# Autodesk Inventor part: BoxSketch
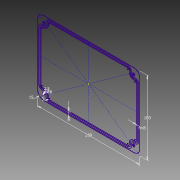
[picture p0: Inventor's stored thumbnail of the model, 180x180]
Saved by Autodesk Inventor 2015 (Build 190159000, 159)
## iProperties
Created: 2014-07
Part Number: BoxSketch
Material: Generic
Document SubType Name: Modeling
Designer: Gavin
Density: 1 g/cm^3
Appearance: Default
Author: Gavin
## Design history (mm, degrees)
sketch "Sketch1"
  geometry: L1 (135, 90)-(-135, 90); L2 (-150, 75)-(-150, -75); L3 (-135, -90)-(135, -90); L4 (150, -75)-(150, 75); L5 (150, 90)-(-150, -90); L6 (-150, 90)-(150, -90); L7 (121, -82)-(-121, -82); L8 (-142, -61)-(-142, 61); L9 (-121, 82)-(121, 82); L10 (142, 61)-(142, -61); L11 (124, -79)-(124, -75); L12 (135, -64)-(139, -64); L13 (0, -90)-(0, 90); L14 (150, 0)-(-150, 0); L15 (-124, -79)-(-124, -75); L16 (-135, -64)-(-139, -64); L17 (124, 79)-(124, 75); L18 (135, 64)-(139, 64); L19 (-124, 79)-(-124, 75); L20 (-135, 64)-(-139, 64); L21 (-121, -84.5)-(121, -84.5); L22 (126.5, -79)-(126.5, -75); L23 (135, -66.5)-(139, -66.5); L24 (144.5, -61)-(144.5, 61); L25 (139, 66.5)-(135, 66.5); L26 (126.5, 75)-(126.5, 79); L27 (121, 84.5)-(-121, 84.5); L28 (-126.5, 79)-(-126.5, 75); L29 (-135, 66.5)-(-139, 66.5); L30 (-144.5, 61)-(-144.5, -61); L31 (-139, -66.5)-(-135, -66.5); L32 (-126.5, -75)-(-126.5, -79); L33 (121, -87.5)-(-121, -87.5); L34 (-129.5, -79)-(-129.5, -75); L35 (-135, -69.5)-(-139, -69.5); L36 (-147.5, -61)-(-147.5, 61); L37 (-139, 69.5)-(-135, 69.5); L38 (-129.5, 75)-(-129.5, 79); L39 (-121, 87.5)-(121, 87.5); L40 (129.5, 79)-(129.5, 75); L41 (135, 69.5)-(139, 69.5); L42 (147.5, 61)-(147.5, -61); L43 (139, -69.5)-(135, -69.5); L44 (129.5, -75)-(129.5, -79); C1 r 3 at (135, -75); C2 r 3 at (-135, -75); C3 r 3 at (135, 75); C4 r 3 at (-135, 75); A1 r 15 centre (135, -75) between (135, -90) and (150, -75); A2 r 15 centre (-135, -75) between (-150, -75) and (-135, -90); A3 r 15 centre (135, 75) between (150, 75) and (135, 90); A4 r 15 centre (-135, 75) between (-135, 90) and (-150, 75); A5 r 11 centre (135, -75) between (135, -64) and (124, -75); A6 r 3 centre (121, -79) between (121, -82) and (124, -79); A7 r 3 centre (139, -61) between (139, -64) and (142, -61); A8 r 3 centre (-121, -79) between (-124, -79) and (-121, -82); A9 r 11 centre (-135, -75) between (-124, -75) and (-135, -64); A10 r 3 centre (-139, -61) between (-142, -61) and (-139, -64); A11 r 3 centre (121, 79) between (124, 79) and (121, 82); A12 r 11 centre (135, 75) between (124, 75) and (135, 64); A13 r 3 centre (139, 61) between (142, 61) and (139, 64); A14 r 3 centre (-121, 79) between (-121, 82) and (-124, 79); A15 r 11 centre (-135, 75) between (-135, 64) and (-124, 75); A16 r 3 centre (-139, 61) between (-139, 64) and (-142, 61); A17 r 5.5 centre (121, -79) between (121, -84.5) and (126.5, -79); A18 r 8.5 centre (135, -75) between (135, -66.5) and (126.5, -75); A19 r 5.5 centre (139, -61) between (139, -66.5) and (144.5, -61); A20 r 5.5 centre (139, 61) between (144.5, 61) and (139, 66.5); A21 r 8.5 centre (135, 75) between (126.5, 75) and (135, 66.5); A22 r 5.5 centre (121, 79) between (126.5, 79) and (121, 84.5); A23 r 5.5 centre (-121, 79) between (-121, 84.5) and (-126.5, 79); A24 r 8.5 centre (-135, 75) between (-135, 66.5) and (-126.5, 75); A25 r 5.5 centre (-139, 61) between (-139, 66.5) and (-144.5, 61); A26 r 5.5 centre (-139, -61) between (-144.5, -61) and (-139, -66.5); A27 r 8.5 centre (-135, -75) between (-126.5, -75) and (-135, -66.5); A28 r 5.5 centre (-121, -79) between (-126.5, -79) and (-121, -84.5); A29 r 8.5 centre (-121, -79) between (-129.5, -79) and (-121, -87.5); A30 r 5.5 centre (-135, -75) between (-129.5, -75) and (-135, -69.5); A31 r 8.5 centre (-139, -61) between (-147.5, -61) and (-139, -69.5); A32 r 8.5 centre (-139, 61) between (-139, 69.5) and (-147.5, 61); A33 r 5.5 centre (-135, 75) between (-135, 69.5) and (-129.5, 75); A34 r 8.5 centre (-121, 79) between (-121, 87.5) and (-129.5, 79); A35 r 8.5 centre (121, 79) between (129.5, 79) and (121, 87.5); A36 r 5.5 centre (135, 75) between (129.5, 75) and (135, 69.5); A37 r 8.5 centre (139, 61) between (147.5, 61) and (139, 69.5); A38 r 8.5 centre (139, -61) between (139, -69.5) and (147.5, -61); A39 r 5.5 centre (135, -75) between (135, -69.5) and (129.5, -75); A40 r 8.5 centre (121, -79) between (121, -87.5) and (129.5, -79); 1 further point
  constraints: 88 end point, 80 point on circle, 44 centre point, 27 symmetric about line, 14 tangent, 8 parallel, 8 point on line, 7 perpendicular, 6 midpoint, 4 equal radius, 1 coincident, 1 horizontal, 1 vertical, 58 other
  dimensions: "Length" = 300 distance of L6.end L5.end; "Width" = 180 distance of L5.end L6.start; "d2" = 15 radius of A1; "d3" = 8 distance between parallel lines of L3 L7; "ScrewDia" = 6 diameter of C1; "d5" = 3 radius of A6; "d6" = 8 radial gap between concentric circles of A5 C1 (= d3); "d7" = 8 distance between parallel lines of L2 L8 (= d3); "d8" = 3 radial gap between concentric circles of A18 A39; "d9" = 2.5 radial gap between concentric circles of A39 C1
